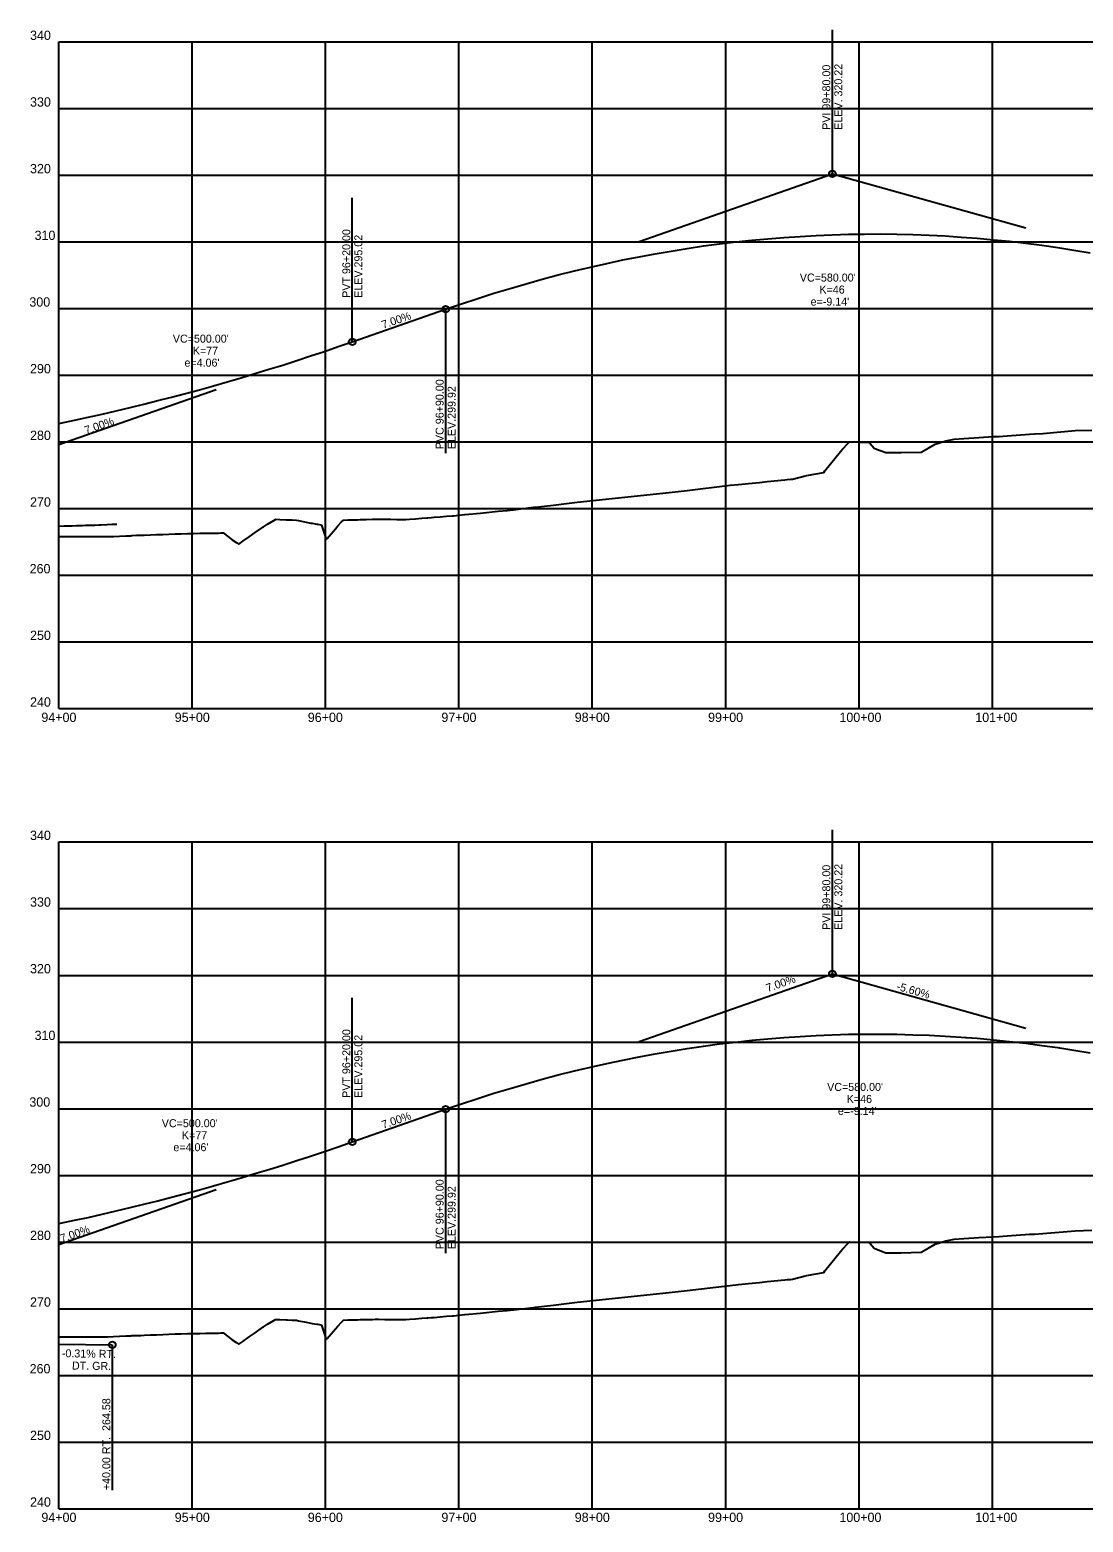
# Model space of a CAD drawing. Extents: x 1709196 to 1718257, y 543790 to 550544.
# Drawn here: x 1712468 to 1713258, y 547357 to 548476 of the extents above; entities that cross this region are included whole.
import ezdxf

# ---------------------------------------------------------------- set-up
doc = ezdxf.new("R2010")
doc.units = 0
for name, color, linetype in [('R_Axis', 7, 'Continuous'), ('R_Axis Annot', 7, 'Continuous'), ('R_ConcretePattern', 7, 'Continuous'), ('R_Exist Surface', 7, 'Continuous'), ('R_Grid', 7, 'Continuous'), ('R_Horz Alg Annot', 7, 'Continuous'), ('R_Proposed Const Limits_Fill', 7, 'Continuous'), ('R_Vert Alg', 7, 'Continuous'), ('R_Vert Alg Annot', 7, 'Continuous')]:
    doc.layers.add(name, color=color, linetype=linetype)

msp = doc.modelspace()

# ---------------------------------------------------------------- linework, layer by layer
at = {"layer": 'R_Axis'}
for p, q in [((1712489.7, 547967.3), (1712489.7, 548467.3)), ((1712489.7, 547967.3), (1714289.7, 547967.3)), ((1712489.7, 547367.3), (1712489.7, 547867.3)), ((1712489.7, 547367.3), (1714289.7, 547367.3))]:
    msp.add_line(p, q, dxfattribs=at)
at = {"layer": 'R_ConcretePattern'}
msp.add_line((1712973.2, 547715.2), (1712973.2, 547715.2), dxfattribs=at)
msp.add_line((1712973.2, 547715.2), (1712973.2, 547715.2), dxfattribs=at)
at = {"layer": 'R_Exist Surface'}
for points in [[(1712489.7, 548096.3), (1712489.8, 548096.3), (1712493.6, 548096.3), (1712497.1, 548096.3), (1712498.2, 548096.3), (1712502.8, 548096.3), (1712507.4, 548096.3), (1712507.6, 548096.3), (1712512.1, 548096.3), (1712516.7, 548096.3), (1712519.8, 548096.3), (1712521.3, 548096.3), (1712525.9, 548096.3), (1712526, 548096.3), (1712530.6, 548096.5), (1712535.2, 548096.7), (1712539.8, 548096.9), (1712543.7, 548097), (1712544.4, 548097.1), (1712547.9, 548097.3), (1712549.1, 548097.3), (1712551, 548097.3), (1712553.7, 548097.5), (1712558.3, 548097.6), (1712562.9, 548097.8), (1712567.6, 548098), (1712572.2, 548098.2), (1712576.8, 548098.5), (1712577.6, 548098.5), (1712581.4, 548098.5), (1712586.1, 548098.6), (1712590.7, 548098.7), (1712595.3, 548098.8), (1712599.9, 548098.9), (1712604.6, 548098.9), (1712609.2, 548099), (1712609.3, 548099), (1712611, 548099.1), (1712612.8, 548099.2), (1712613.8, 548098.4), (1712618.4, 548095), (1712619.7, 548094), (1712623.1, 548091.7), (1712624.6, 548090.7), (1712627.7, 548092.8), (1712632.3, 548096.1), (1712636.9, 548099.3), (1712641.6, 548102.6), (1712642.7, 548103.4), (1712643.1, 548103.7), (1712646.2, 548105.6), (1712650.8, 548108.5), (1712652, 548109.2), (1712652.2, 548109.3), (1712655.4, 548109.2), (1712660.1, 548109), (1712661, 548109), (1712664.7, 548108.8), (1712667.9, 548108.6), (1712669.3, 548108.3), (1712673.9, 548107.4), (1712678.6, 548106.5), (1712679.5, 548106.3), (1712683.2, 548105.7), (1712683.9, 548105.6), (1712686.1, 548105.1), (1712686.5, 548105), (1712687.8, 548101.2), (1712690.1, 548094.3), (1712690.2, 548094.1), (1712690.9, 548095), (1712692.4, 548096.7), (1712697.1, 548102.2), (1712698.9, 548104.3), (1712701.7, 548107.3), (1712703, 548108.7), (1712706.3, 548108.9), (1712709.8, 548109), (1712710.9, 548109), (1712713.6, 548109), (1712715.6, 548109.1), (1712720.2, 548109.2), (1712724.8, 548109.3), (1712726.8, 548109.4), (1712729.4, 548109.4), (1712734.1, 548109.3), (1712738.7, 548109.3), (1712743.2, 548109.2), (1712743.3, 548109.2), (1712746.2, 548109.2), (1712747.9, 548109.2), (1712749.9, 548109.2), (1712752.6, 548109.4), (1712757.2, 548109.7), (1712761.8, 548110.1), (1712765.7, 548110.4), (1712766.4, 548110.4), (1712769.2, 548110.7), (1712771.1, 548110.8), (1712775.7, 548111.2), (1712780.3, 548111.6), (1712784.9, 548111.9), (1712785.7, 548112), (1712789.5, 548112.4), (1712793.9, 548112.9), (1712794.2, 548112.9), (1712805.9, 548113.9), (1712819.1, 548115.4), (1712825.9, 548116), (1712830.6, 548116.5), (1712845.7, 548118.3), (1712847, 548118.5), (1712853.9, 548119.2), (1712860.6, 548120), (1712870.3, 548121.2), (1712878.4, 548122.2), (1712947.3, 548129.5), (1712960.7, 548131), (1712993.1, 548134.8), (1712999.3, 548135.5), (1713006.8, 548136.2), (1713015, 548137), (1713020.9, 548137.6), (1713034.1, 548138.9), (1713035.9, 548139.1), (1713038.4, 548139.3), (1713039.7, 548139.4), (1713050.4, 548142.1), (1713063.2, 548144.5), (1713064.1, 548145.7), (1713075.7, 548160.2), (1713076, 548160.5), (1713077.4, 548162), (1713081.6, 548166.4), (1713082.6, 548167.4), (1713090.1, 548167.2), (1713097.1, 548167), (1713098, 548166.2), (1713101.1, 548162.7), (1713102.8, 548162), (1713109.7, 548159.3), (1713121.3, 548159.3), (1713136.2, 548159.6), (1713142, 548162.9), (1713146.8, 548165.7), (1713154.8, 548168.1), (1713161.1, 548169.5), (1713168.4, 548169.9), (1713179.5, 548170.6), (1713190.3, 548171.3), (1713194.7, 548171.5), (1713200.8, 548171.9), (1713217.5, 548173.1), (1713221.4, 548173.3), (1713227.5, 548173.6), (1713251.9, 548175.8), (1713264.2, 548176.2)], [(1712489.7, 547496.3), (1712489.8, 547496.3), (1712493.6, 547496.3), (1712497.1, 547496.3), (1712498.2, 547496.3), (1712502.8, 547496.3), (1712507.4, 547496.3), (1712507.6, 547496.3), (1712512.1, 547496.3), (1712516.7, 547496.3), (1712519.8, 547496.3), (1712521.3, 547496.3), (1712525.9, 547496.3), (1712526, 547496.3), (1712530.6, 547496.5), (1712535.2, 547496.7), (1712539.8, 547496.9), (1712543.7, 547497), (1712544.4, 547497.1), (1712547.9, 547497.3), (1712549.1, 547497.3), (1712551, 547497.3), (1712553.7, 547497.5), (1712558.3, 547497.6), (1712562.9, 547497.8), (1712567.6, 547498), (1712572.2, 547498.2), (1712576.8, 547498.5), (1712577.6, 547498.5), (1712581.4, 547498.5), (1712586.1, 547498.6), (1712590.7, 547498.7), (1712595.3, 547498.8), (1712599.9, 547498.9), (1712604.6, 547498.9), (1712609.2, 547499), (1712609.3, 547499), (1712611, 547499.1), (1712612.8, 547499.2), (1712613.8, 547498.4), (1712618.4, 547495), (1712619.7, 547494), (1712623.1, 547491.7), (1712624.6, 547490.7), (1712627.7, 547492.8), (1712632.3, 547496.1), (1712636.9, 547499.3), (1712641.6, 547502.6), (1712642.7, 547503.4), (1712643.1, 547503.7), (1712646.2, 547505.6), (1712650.8, 547508.5), (1712652, 547509.2), (1712652.2, 547509.3), (1712655.4, 547509.2), (1712660.1, 547509), (1712661, 547509), (1712664.7, 547508.8), (1712667.9, 547508.6), (1712669.3, 547508.3), (1712673.9, 547507.4), (1712678.6, 547506.5), (1712679.5, 547506.3), (1712683.2, 547505.7), (1712683.9, 547505.6), (1712686.1, 547505.1), (1712686.5, 547505), (1712687.8, 547501.2), (1712690.1, 547494.3), (1712690.2, 547494.1), (1712690.9, 547495), (1712692.4, 547496.7), (1712697.1, 547502.2), (1712698.9, 547504.3), (1712701.7, 547507.3), (1712703, 547508.7), (1712706.3, 547508.9), (1712709.8, 547509), (1712710.9, 547509), (1712713.6, 547509), (1712715.6, 547509.1), (1712720.2, 547509.2), (1712724.8, 547509.3), (1712726.8, 547509.4), (1712729.4, 547509.4), (1712734, 547509.3), (1712738.7, 547509.3), (1712743.2, 547509.2), (1712743.3, 547509.2), (1712746.2, 547509.2), (1712747.9, 547509.2), (1712749.9, 547509.2), (1712752.5, 547509.4), (1712757.2, 547509.7), (1712761.8, 547510.1), (1712765.7, 547510.4), (1712766.4, 547510.4), (1712769.2, 547510.7), (1712771, 547510.8), (1712775.7, 547511.2), (1712780.3, 547511.6), (1712784.9, 547511.9), (1712785.7, 547512), (1712789.5, 547512.4), (1712793.9, 547512.9), (1712794.2, 547512.9), (1712805.9, 547513.9), (1712819.1, 547515.4), (1712825.9, 547516), (1712830.6, 547516.5), (1712845.7, 547518.3), (1712847, 547518.5), (1712853.9, 547519.2), (1712860.5, 547520), (1712870.3, 547521.2), (1712878.4, 547522.2), (1712947.3, 547529.5), (1712960.7, 547531), (1712993.1, 547534.8), (1712999.3, 547535.5), (1713006.8, 547536.2), (1713015, 547537), (1713020.9, 547537.6), (1713034.1, 547538.9), (1713035.9, 547539.1), (1713038.4, 547539.3), (1713039.7, 547539.4), (1713050.4, 547542.1), (1713063.2, 547544.5), (1713064.1, 547545.7), (1713075.7, 547560.2), (1713076, 547560.5), (1713077.4, 547562), (1713081.6, 547566.4), (1713082.6, 547567.4), (1713090.1, 547567.2), (1713097.1, 547567), (1713098, 547566.2), (1713101.1, 547562.7), (1713102.8, 547562), (1713109.7, 547559.3), (1713121.3, 547559.3), (1713136.2, 547559.6), (1713142, 547562.9), (1713146.8, 547565.7), (1713154.8, 547568.1), (1713161.1, 547569.5), (1713168.4, 547569.9), (1713179.5, 547570.6), (1713190.3, 547571.3), (1713194.7, 547571.5), (1713200.8, 547571.9), (1713217.5, 547573.1), (1713221.4, 547573.3), (1713227.5, 547573.6), (1713251.9, 547575.8), (1713264.2, 547576.2)]]:
    msp.add_lwpolyline(points, dxfattribs=at)
at = {"layer": 'R_Grid'}
for p, q in [((1712489.7, 548467.3), (1714289.7, 548467.3)), ((1712489.7, 548467.3), (1714289.7, 548467.3)), ((1712589.7, 547967.3), (1712589.7, 548467.3)), ((1712689.7, 547967.3), (1712689.7, 548467.3)), ((1712789.7, 547967.3), (1712789.7, 548467.3)), ((1712889.7, 547967.3), (1712889.7, 548467.3)), ((1712989.7, 547967.3), (1712989.7, 548467.3)), ((1713089.7, 547967.3), (1713089.7, 548467.3)), ((1713189.7, 547967.3), (1713189.7, 548467.3)), ((1712489.7, 548417.3), (1714289.7, 548417.3)), ((1712489.7, 548367.3), (1714289.7, 548367.3)), ((1712489.7, 548317.3), (1714289.7, 548317.3)), ((1712489.7, 548267.3), (1714289.7, 548267.3)), ((1712489.7, 548217.3), (1714289.7, 548217.3)), ((1712489.7, 548167.3), (1714289.7, 548167.3)), ((1712489.7, 548117.3), (1714289.7, 548117.3)), ((1712489.7, 548067.3), (1714289.7, 548067.3)), ((1712489.7, 548017.3), (1714289.7, 548017.3)), ((1712489.7, 547867.3), (1714289.7, 547867.3)), ((1712489.7, 547867.3), (1714289.7, 547867.3)), ((1712589.7, 547367.3), (1712589.7, 547867.3)), ((1712689.7, 547367.3), (1712689.7, 547867.3)), ((1712789.7, 547367.3), (1712789.7, 547867.3)), ((1712889.7, 547367.3), (1712889.7, 547867.3)), ((1712989.7, 547367.3), (1712989.7, 547867.3)), ((1713089.7, 547367.3), (1713089.7, 547867.3)), ((1713189.7, 547367.3), (1713189.7, 547867.3)), ((1712489.7, 547817.3), (1714289.7, 547817.3)), ((1712489.7, 547767.3), (1714289.7, 547767.3)), ((1712489.7, 547717.3), (1714289.7, 547717.3)), ((1712489.7, 547667.3), (1714289.7, 547667.3)), ((1712489.7, 547617.3), (1714289.7, 547617.3)), ((1712489.7, 547567.3), (1714289.7, 547567.3)), ((1712489.7, 547517.3), (1714289.7, 547517.3)), ((1712489.7, 547467.3), (1714289.7, 547467.3)), ((1712489.7, 547417.3), (1714289.7, 547417.3))]:
    msp.add_line(p, q, dxfattribs=at)
at = {"layer": 'R_Proposed Const Limits_Fill'}
msp.add_lwpolyline([(1712489.7, 548104.2), (1712493.6, 548104.3), (1712496.6, 548104.4), (1712498.2, 548104.5), (1712499.7, 548104.5), (1712502.8, 548104.6), (1712507.4, 548104.7), (1712509.7, 548104.8), (1712512.1, 548104.8), (1712516.7, 548105), (1712519.7, 548105.1), (1712521.3, 548105.2), (1712525.9, 548105.4), (1712529.7, 548105.6), (1712530.6, 548105.6), (1712533.1, 548105.7)], dxfattribs=at)
at = {"layer": 'R_Vert Alg'}
for p, q in [((1712924.7, 548317.6), (1713069.7, 548368.4)), ((1713069.7, 548368.4), (1713214.7, 548327.8)), ((1712709.7, 548242.4), (1712779.7, 548266.9)), ((1712489.7, 548165.4), (1712607.6, 548206.7)), ((1712924.7, 547717.6), (1713069.7, 547768.4)), ((1713069.7, 547768.4), (1713214.7, 547727.8)), ((1713231.4, 547717.3), (1713239.7, 547717.3)), ((1712709.7, 547642.4), (1712779.7, 547666.9)), ((1712489.7, 547565.4), (1712607.6, 547606.7)), ((1712489.7, 547490.8), (1712529.7, 547490.2)), ((1712489.7, 547490.8), (1712529.7, 547490.2))]:
    msp.add_line(p, q, dxfattribs=at)
for points in [[(1712779.7, 548266.9), (1712791.7, 548271), (1712803.8, 548275), (1712815.9, 548278.9), (1712828, 548282.5), (1712840.1, 548286), (1712852.2, 548289.4), (1712864.2, 548292.6), (1712876.3, 548295.6), (1712888.4, 548298.5), (1712900.5, 548301.2), (1712912.6, 548303.8), (1712924.7, 548306.2), (1712936.7, 548308.5), (1712948.8, 548310.5), (1712960.9, 548312.5), (1712973, 548314.3), (1712985.1, 548315.9), (1712997.2, 548317.3), (1713009.2, 548318.6), (1713021.3, 548319.7), (1713033.4, 548320.7), (1713045.5, 548321.5), (1713057.6, 548322.2), (1713081.7, 548323.1), (1713093.8, 548323.2), (1713105.9, 548323.3), (1713118, 548323.1), (1713130.1, 548322.8), (1713142.2, 548322.4), (1713154.2, 548321.8), (1713166.3, 548321), (1713178.4, 548320.1), (1713190.5, 548319), (1713202.6, 548317.8), (1713214.7, 548316.4), (1713226.7, 548314.8), (1713238.8, 548313.1), (1713250.9, 548311.2), (1713263, 548309.2)], [(1712489.7, 548181.1), (1712490.9, 548181.4), (1712501.3, 548183.6), (1712511.7, 548185.8), (1712522.2, 548188.2), (1712532.6, 548190.6), (1712543, 548193.1), (1712553.4, 548195.6), (1712563.8, 548198.3), (1712574.2, 548200.9), (1712584.7, 548203.7), (1712595.1, 548206.5), (1712605.5, 548209.5), (1712615.9, 548212.4), (1712626.3, 548215.5), (1712636.7, 548218.6), (1712647.2, 548221.8), (1712657.6, 548225), (1712668, 548228.4), (1712678.4, 548231.8), (1712688.8, 548235.2), (1712699.2, 548238.8), (1712709.7, 548242.4)], [(1712779.7, 547666.9), (1712791.7, 547671), (1712803.8, 547675), (1712815.9, 547678.9), (1712828, 547682.5), (1712840.1, 547686), (1712852.2, 547689.4), (1712864.2, 547692.6), (1712876.3, 547695.6), (1712888.4, 547698.5), (1712900.5, 547701.2), (1712912.6, 547703.8), (1712924.7, 547706.2), (1712936.7, 547708.5), (1712948.8, 547710.5), (1712960.9, 547712.5), (1712973, 547714.3), (1712985.1, 547715.9), (1712997.2, 547717.3), (1713009.2, 547718.6), (1713021.3, 547719.7), (1713033.4, 547720.7), (1713045.5, 547721.5), (1713057.6, 547722.2), (1713081.7, 547723.1), (1713093.8, 547723.2), (1713105.9, 547723.3), (1713118, 547723.1), (1713130.1, 547722.8), (1713142.2, 547722.4), (1713154.2, 547721.8), (1713166.3, 547721), (1713178.4, 547720.1), (1713190.5, 547719), (1713202.6, 547717.8), (1713214.7, 547716.4), (1713226.7, 547714.8), (1713238.8, 547713.1), (1713250.9, 547711.2), (1713263, 547709.2)], [(1712939.7, 547709), (1712948.8, 547710.5), (1712960.9, 547712.5), (1712973, 547714.3), (1712985.1, 547715.9), (1712997.2, 547717.3), (1713009.2, 547718.6), (1713009.6, 547718.6)], [(1713009.8, 547718.7), (1713021.3, 547719.7), (1713033.4, 547720.7), (1713045.5, 547721.5), (1713057.6, 547722.2), (1713081.7, 547723.1), (1713093.8, 547723.2), (1713105.9, 547723.3), (1713118, 547723.1), (1713130.1, 547722.8), (1713142.2, 547722.4), (1713154.2, 547721.8), (1713166.3, 547721), (1713169.6, 547720.8)], [(1713169.8, 547720.8), (1713178.4, 547720.1), (1713190.5, 547719), (1713202.6, 547717.8), (1713214.7, 547716.4), (1713226.7, 547714.8), (1713238.8, 547713.1), (1713239.7, 547713)], [(1712489.7, 547581.1), (1712490.9, 547581.4), (1712501.3, 547583.6), (1712511.7, 547585.8), (1712522.2, 547588.2), (1712532.6, 547590.6), (1712543, 547593.1), (1712553.4, 547595.6), (1712563.8, 547598.3), (1712574.2, 547600.9), (1712584.7, 547603.7), (1712595.1, 547606.5), (1712605.5, 547609.5), (1712615.9, 547612.4), (1712626.3, 547615.5), (1712636.7, 547618.6), (1712647.2, 547621.8), (1712657.6, 547625), (1712668, 547628.4), (1712678.4, 547631.8), (1712688.8, 547635.2), (1712699.2, 547638.8), (1712709.7, 547642.4)]]:
    msp.add_lwpolyline(points, dxfattribs=at)
msp.add_circle((1712529.7, 547490.2), 2.5, dxfattribs=at)
msp.add_circle((1712529.7, 547490.2), 2.5, dxfattribs=at)
at = {"layer": 'R_Vert Alg Annot'}
for p, q in [((1713069.7, 548398.4), (1713069.7, 548476.4)), ((1713069.7, 548368.4), (1713069.7, 548398.4)), ((1712709.7, 548272.4), (1712709.7, 548350.4)), ((1712709.7, 548242.4), (1712709.7, 548272.4)), ((1712779.7, 548266.9), (1712779.7, 548236.9)), ((1712779.7, 548236.9), (1712779.7, 548158.9)), ((1713069.7, 547798.4), (1713069.7, 547876.4)), ((1713069.7, 547768.4), (1713069.7, 547798.4)), ((1712709.7, 547672.4), (1712709.7, 547750.4)), ((1712709.7, 547642.4), (1712709.7, 547672.4)), ((1712779.7, 547666.9), (1712779.7, 547636.9)), ((1712779.7, 547636.9), (1712779.7, 547558.9)), ((1712529.7, 547490.2), (1712529.7, 547465.2)), ((1712529.7, 547490.2), (1712529.7, 547465.2)), ((1712529.7, 547465.2), (1712529.7, 547381.2)), ((1712529.7, 547465.2), (1712529.7, 547381.2))]:
    msp.add_line(p, q, dxfattribs=at)
for centre in [(1713069.7, 548368.4), (1712779.7, 548266.9), (1712709.7, 548242.4), (1713069.7, 547768.4), (1712779.7, 547666.9), (1712709.7, 547642.4)]:
    msp.add_circle(centre, 2.5, dxfattribs=at)

# ---------------------------------------------------------------- texts
at = {"layer": 'R_Axis Annot'}
for s, height, p in [('340', 7, (1712468, 548468.8)), ('340', 7, (1712468, 548468.8)), ('330', 7, (1712468, 548418.8)), ('320', 7, (1712468, 548368.8)), ('310', 7, (1712471.4, 548318.8)), ('300', 7, (1712467.5, 548268.8)), ('290', 7, (1712468, 548218.8)), ('280', 7, (1712468, 548168.8)), ('270', 7, (1712468, 548118.8)), ('260', 7, (1712467.7, 548068.8)), ('250', 7, (1712468, 548018.8)), ('240', 7, (1712468, 547968.8)), ('94+00', 7, (1712476.5, 547957.3)), ('-', 0.0001, (1712489.7, 547967.3)), ('95+00', 7, (1712576.5, 547957.3)), ('96+00', 7, (1712676.3, 547957.3)), ('97+00', 7, (1712776.5, 547957.3)), ('98+00', 7, (1712876.5, 547957.3)), ('99+00', 7, (1712976.5, 547957.3)), ('100+00', 7, (1713075, 547957.3)), ('101+00', 7, (1713176.9, 547957.3)), ('340', 7, (1712468, 547868.8)), ('340', 7, (1712468, 547868.8)), ('330', 7, (1712468, 547818.8)), ('320', 7, (1712468, 547768.8)), ('310', 7, (1712471.4, 547718.8)), ('300', 7, (1712467.5, 547668.8)), ('290', 7, (1712468, 547618.8)), ('280', 7, (1712468, 547568.8)), ('270', 7, (1712468, 547518.8)), ('-', 0.0005, (1712939.7, 547517.3)), ('260', 7, (1712467.7, 547468.8)), ('250', 7, (1712468, 547418.8)), ('240', 7, (1712468, 547368.8)), ('94+00', 7, (1712476.5, 547357.3)), ('-', 0.0001, (1712489.7, 547367.3)), ('-', 0.0001, (1712489.7, 547367.3)), ('-', 0.0001, (1712489.7, 547367.3)), ('-', 0.0001, (1712489.7, 547367.3)), ('-', 0.0001, (1712489.7, 547367.3)), ('-', 0.0001, (1712489.7, 547367.3)), ('-', 0.0001, (1712489.7, 547367.3)), ('-', 0.0001, (1712489.7, 547367.3)), ('-', 0.0001, (1712489.7, 547367.3)), ('-', 0.0001, (1712489.7, 547367.3)), ('-', 0.0001, (1712489.7, 547367.3)), ('-', 0.0001, (1712489.7, 547367.3)), ('-', 0.0001, (1712489.7, 547367.3)), ('-', 0.0001, (1712489.7, 547367.3)), ('-', 0.0001, (1712489.7, 547367.3)), ('-', 0.0001, (1712489.7, 547367.3)), ('-', 0.0001, (1712489.7, 547367.3)), ('-', 0.0001, (1712489.7, 547367.3)), ('-', 0.0001, (1712489.7, 547367.3)), ('-', 0.0001, (1712489.7, 547367.3)), ('95+00', 7, (1712576.5, 547357.3)), ('96+00', 7, (1712676.3, 547357.3)), ('97+00', 7, (1712776.5, 547357.3)), ('98+00', 7, (1712876.5, 547357.3)), ('99+00', 7, (1712976.5, 547357.3)), ('100+00', 7, (1713075, 547357.3)), ('101+00', 7, (1713176.9, 547357.3))]:
    msp.add_text(s, height=height, dxfattribs=at).set_placement(p)
at = {"layer": 'R_Horz Alg Annot'}
for s, rotation, p in [('7.00%', 19.29, (1712510.1, 548173)), ('7.00%', 19.29, (1713021.2, 547754.7)), ('-5.60%', 344.3578, (1713117.4, 547756.5)), ('7.00%', 19.29, (1712491.9, 547566.9))]:
    msp.add_text(s, height=6, rotation=rotation, dxfattribs=at).set_placement(p)
at = {"layer": 'R_Vert Alg Annot'}
for s, rotation, p in [('PVI 99+80.00', 90, (1713068.2, 548401.4)), ('ELEV. 320.22', 90, (1713077.2, 548401.4)), ('PVT 96+20.00', 90, (1712708.2, 548275.4)), ('ELEV.295.02', 90, (1712717.2, 548275.4)), ('7.00%', 19.29, (1712732.9, 548252.1)), ('PVC 96+90.00', 90, (1712778.2, 548161.9)), ('ELEV.299.92', 90, (1712787.2, 548161.9)), ('PVI 99+80.00', 90, (1713068.2, 547801.4)), ('ELEV. 320.22', 90, (1713077.2, 547801.4)), ('PVT 96+20.00', 90, (1712708.2, 547675.4)), ('ELEV.295.02', 90, (1712717.2, 547675.4)), ('7.00%', 19.29, (1712732.9, 547652.1)), ('PVC 96+90.00', 90, (1712778.2, 547561.9)), ('ELEV.299.92', 90, (1712787.2, 547561.9)), ('-0.31% RT. ', 359.1127, (1712491.8, 547480.9)), ('DT. GR.', 359.1127, (1712499.4, 547471.7)), ('+40.00 RT.  264.58', 90, (1712528.2, 547381.2)), ('+40.00 RT.  264.58', 90, (1712528.2, 547381.2))]:
    msp.add_text(s, height=6, rotation=rotation, dxfattribs=at).set_placement(p)
for s, p in [("VC=580.00'", (1713045.3, 548287.6)), ("e=-9.14'", (1713053.4, 548269.6)), ('K=46', (1713060, 548278.6)), ("VC=500.00'", (1712575.1, 548241.8)), ('K=77', (1712590.1, 548232.8)), ("e=4.06'", (1712583.8, 548223.8)), ("VC=580.00'", (1713065.8, 547680.6)), ('K=46', (1713080.5, 547671.6)), ("VC=500.00'", (1712566.8, 547653.4)), ("e=-9.14'", (1713073.9, 547662.6)), ('K=77', (1712581.9, 547644.4)), ("e=4.06'", (1712575.5, 547635.4))]:
    msp.add_text(s, height=6, dxfattribs=at).set_placement(p)

doc.saveas('drawing.dxf')
